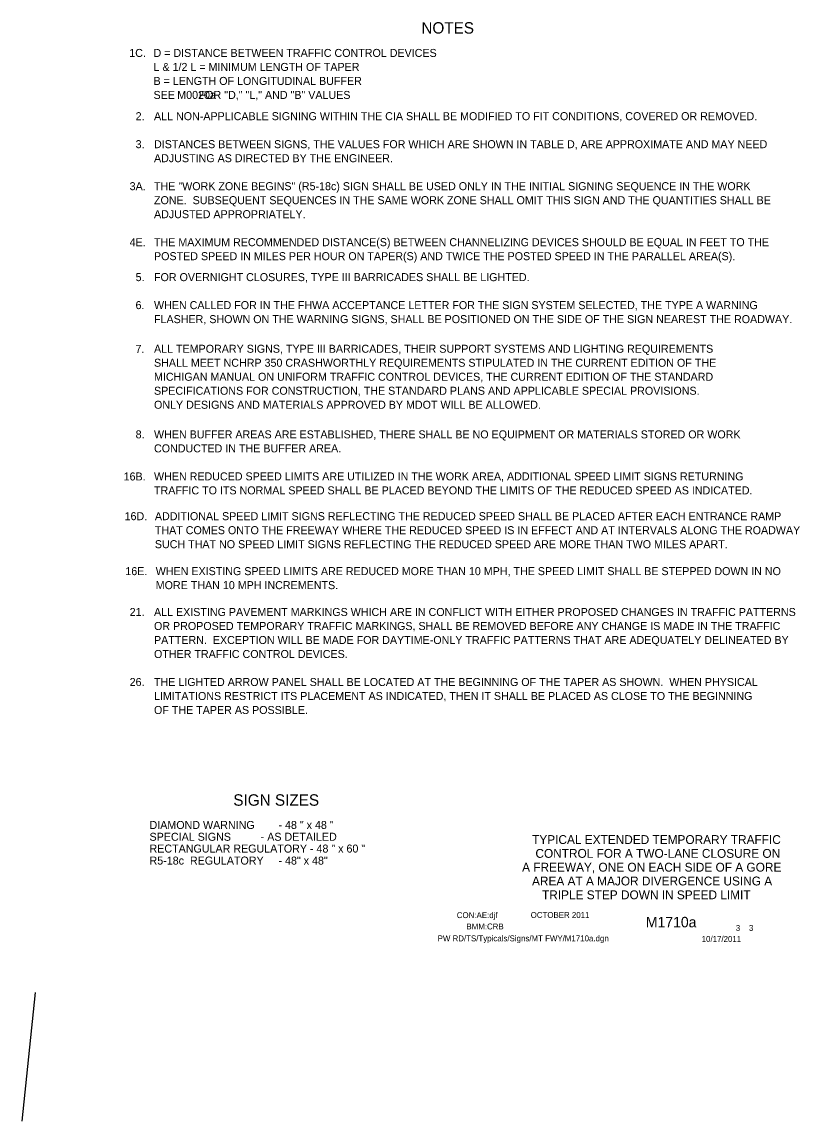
# Model space of a CAD drawing. Extents: x 16630 to 19509, y 5576 to 6998.
# Drawn here: x 18692 to 19509, y 5745 to 6899 of the extents above; entities that cross this region are included whole.
import ezdxf

# ---------------------------------------------------------------- set-up
doc = ezdxf.new("R2010")
doc.units = 0
for name, color, linetype in [('BORDER', 7, 'Continuous'), ('BORDER_SIGNAL_WO', 7, 'Continuous'), ('TYPICAL_TEXT_DIMEN_PR', 7, 'Continuous')]:
    doc.layers.add(name, color=color, linetype=linetype)

msp = doc.modelspace()

# ---------------------------------------------------------------- linework, layer by layer
at = {"layer": 'TYPICAL_TEXT_DIMEN_PR'}
msp.add_line((18705.8, 5880), (18692, 5745), dxfattribs=at)

# ---------------------------------------------------------------- texts
at = {"layer": 'BORDER'}
for s, p in [('TYPICAL EXTENDED TEMPORARY TRAFFIC', (19227.8, 6035.9)), ('CONTROL FOR A TWO-LANE CLOSURE ON', (19231.3, 6021.4)), ('A FREEWAY, ONE ON EACH SIDE OF A GORE', (19217.3, 6006.9)), ('AREA AT A MAJOR DIVERGENCE USING A', (19227.7, 5992.4)), ('TRIPLE STEP DOWN IN SPEED LIMIT', (19238.2, 5977.9))]:
    msp.add_text(s, height=9.3, dxfattribs=at).set_placement(p)
at = {"layer": 'BORDER_SIGNAL_WO'}
for s, height, p in [('CON:AE:djf  ', 6.2, (19148.7, 5958.1)), ('    OCTOBER 2011', 6.2, (19217.1, 5958.3)), ('    M1710a   ', 11, (19330.9, 5948.4)), ('BMM:CRB', 6.2, (19158.8, 5946.2)), (' 3    3 ', 6.2, (19439.4, 5944.7)), ('PW RD/TS/Typicals/Signs/MT FWY/M1710a.dgn      ', 6.2, (19128.6, 5933.7)), ('10/17/2011', 6.2, (19405.9, 5933.1))]:
    msp.add_text(s, height=height, dxfattribs=at).set_placement(p)
at = {"layer": 'TYPICAL_TEXT_DIMEN_PR'}
for s, height, p in [('NOTES', 12, (19111.5, 6886.8)), ('1C.', 8.4, (18804.7, 6862.3)), ('D = DISTANCE BETWEEN TRAFFIC CONTROL DEVICES', 8.4, (18830.2, 6862.3)), ('L & 1/2 L = MINIMUM LENGTH OF TAPER', 8.4, (18830.2, 6847.6)), ('B = LENGTH OF LONGITUDINAL BUFFER', 8.4, (18830.2, 6832.9)), ('SEE        FOR "D," "L," AND "B" VALUES', 8.4, (18830.2, 6818.2)), ('M0020a', 8.4, (18855.1, 6818.2)), ('2.', 8.4, (18811.4, 6795.9)), ('ALL NON-APPLICABLE SIGNING WITHIN THE CIA SHALL BE MODIFIED TO FIT CONDITIONS, COVERED OR REMOVED.', 8.4, (18830.7, 6795.9)), ('3.', 8.4, (18811.4, 6766.5)), ('DISTANCES BETWEEN SIGNS, THE VALUES FOR WHICH ARE SHOWN IN TABLE D, ARE APPROXIMATE AND MAY NEED', 8.4, (18830.7, 6766.5)), ('ADJUSTING AS DIRECTED BY THE ENGINEER.', 8.4, (18830.7, 6751.8)), ('3A.', 8.4, (18805.1, 6722.4)), ('THE "WORK ZONE BEGINS" (R5-18c) SIGN SHALL BE USED ONLY IN THE INITIAL SIGNING SEQUENCE IN THE WORK', 8.4, (18830.7, 6722.4)), ('ZONE.  SUBSEQUENT SEQUENCES IN THE SAME WORK ZONE SHALL OMIT THIS SIGN AND THE QUANTITIES SHALL BE', 8.4, (18830.7, 6707.7)), ('ADJUSTED APPROPRIATELY.', 8.4, (18830.7, 6693)), ('4E.', 8.4, (18805.1, 6663.6)), ('THE MAXIMUM RECOMMENDED DISTANCE(S) BETWEEN CHANNELIZING DEVICES SHOULD BE EQUAL IN FEET TO THE', 8.4, (18830.7, 6663.6)), ('POSTED SPEED IN MILES PER HOUR ON TAPER(S) AND TWICE THE POSTED SPEED IN THE PARALLEL AREA(S).', 8.4, (18830.7, 6648.9)), ('5.', 8.4, (18811.4, 6626.9)), ('FOR OVERNIGHT CLOSURES, TYPE III BARRICADES SHALL BE LIGHTED.', 8.4, (18830.7, 6626.9)), ('6.', 8.4, (18811.3, 6597.5)), ('WHEN CALLED FOR IN THE FHWA ACCEPTANCE LETTER FOR THE SIGN SYSTEM SELECTED, THE TYPE A WARNING ', 8.4, (18830.7, 6597.5)), ('FLASHER, SHOWN ON THE WARNING SIGNS, SHALL BE POSITIONED ON THE SIDE OF THE SIGN NEAREST THE ROADWAY.', 8.4, (18830.7, 6582.8)), ('7.', 8.4, (18811.3, 6551.6)), ('ALL TEMPORARY SIGNS, TYPE III BARRICADES, THEIR SUPPORT SYSTEMS AND LIGHTING REQUIREMENTS', 8.4, (18830.7, 6551.7)), ('SHALL MEET NCHRP 350 CRASHWORTHLY REQUIREMENTS STIPULATED IN THE CURRENT EDITION OF THE', 8.4, (18830.7, 6537)), ('MICHIGAN MANUAL ON UNIFORM TRAFFIC CONTROL DEVICES, THE CURRENT EDITION OF THE STANDARD', 8.4, (18830.7, 6522.3)), ('SPECIFICATIONS FOR CONSTRUCTION, THE STANDARD PLANS AND APPLICABLE SPECIAL PROVISIONS.', 8.4, (18830.7, 6507.6)), ('ONLY DESIGNS AND MATERIALS APPROVED BY MDOT WILL BE ALLOWED.', 8.4, (18830.7, 6492.9)), ('8.', 8.4, (18811.4, 6461.8)), ('WHEN BUFFER AREAS ARE ESTABLISHED, THERE SHALL BE NO EQUIPMENT OR MATERIALS STORED OR WORK     ', 8.4, (18830.7, 6461.8)), ('CONDUCTED IN THE BUFFER AREA.', 8.4, (18830.7, 6447.1)), ('16B.', 8.4, (18798.8, 6417.6)), ('WHEN REDUCED SPEED LIMITS ARE UTILIZED IN THE WORK AREA, ADDITIONAL SPEED LIMIT SIGNS RETURNING', 8.4, (18830.7, 6417.7)), ('TRAFFIC TO ITS NORMAL SPEED SHALL BE PLACED BEYOND THE LIMITS OF THE REDUCED SPEED AS INDICATED.', 8.4, (18830.7, 6403)), ('16D.', 8.4, (18799.8, 6375.9)), ('ADDITIONAL SPEED LIMIT SIGNS REFLECTING THE REDUCED SPEED SHALL BE PLACED AFTER EACH ENTRANCE RAMP', 8.4, (18831.6, 6375.9)), ('THAT COMES ONTO THE FREEWAY WHERE THE REDUCED SPEED IS IN EFFECT AND AT INTERVALS ALONG THE ROADWAY', 8.4, (18831.6, 6361.2)), ('SUCH THAT NO SPEED LIMIT SIGNS REFLECTING THE REDUCED SPEED ARE MORE THAN TWO MILES APART.', 8.4, (18831.6, 6346.5)), ('16E.', 8.4, (18800.6, 6318.2)), ('WHEN EXISTING SPEED LIMITS ARE REDUCED MORE THAN 10 MPH, THE SPEED LIMIT SHALL BE STEPPED DOWN IN NO', 8.4, (18832.5, 6318.2)), ('MORE THAN 10 MPH INCREMENTS.', 8.4, (18832.5, 6303.5)), ('21.', 8.4, (18805.1, 6275.3)), ('ALL EXISTING PAVEMENT MARKINGS WHICH ARE IN CONFLICT WITH EITHER PROPOSED CHANGES IN TRAFFIC PATTERNS', 8.4, (18830.7, 6275.3)), ('OR PROPOSED TEMPORARY TRAFFIC MARKINGS, SHALL BE REMOVED BEFORE ANY CHANGE IS MADE IN THE TRAFFIC', 8.4, (18830.7, 6260.6)), ('PATTERN.  EXCEPTION WILL BE MADE FOR DAYTIME-ONLY TRAFFIC PATTERNS THAT ARE ADEQUATELY DELINEATED BY', 8.4, (18830.7, 6245.9)), ('OTHER TRAFFIC CONTROL DEVICES.', 8.4, (18830.7, 6231.2)), ('26.', 8.4, (18805.1, 6201.8)), ('THE LIGHTED ARROW PANEL SHALL BE LOCATED AT THE BEGINNING OF THE TAPER AS SHOWN.  WHEN PHYSICAL', 8.4, (18830.7, 6201.8)), ('LIMITATIONS RESTRICT ITS PLACEMENT AS INDICATED, THEN IT SHALL BE PLACED AS CLOSE TO THE BEGINNING', 8.4, (18830.7, 6187.1)), ('OF THE TAPER AS POSSIBLE.', 8.4, (18830.7, 6172.4)), ('SIGN SIZES', 12, (18914, 6076.1)), ('DIAMOND WARNING        - 48 " x 48 "', 8.4, (18826, 6051.7)), ('SPECIAL SIGNS          - AS DETAILED', 8.4, (18826, 6039.3)), ('RECTANGULAR REGULATORY - 48 " x 60 "', 8.4, (18826, 6026.9)), ('R5-18c  REGULATORY     - 48" x 48"', 8.4, (18826, 6014.3))]:
    msp.add_text(s, height=height, dxfattribs=at).set_placement(p)

doc.saveas('drawing.dxf')
